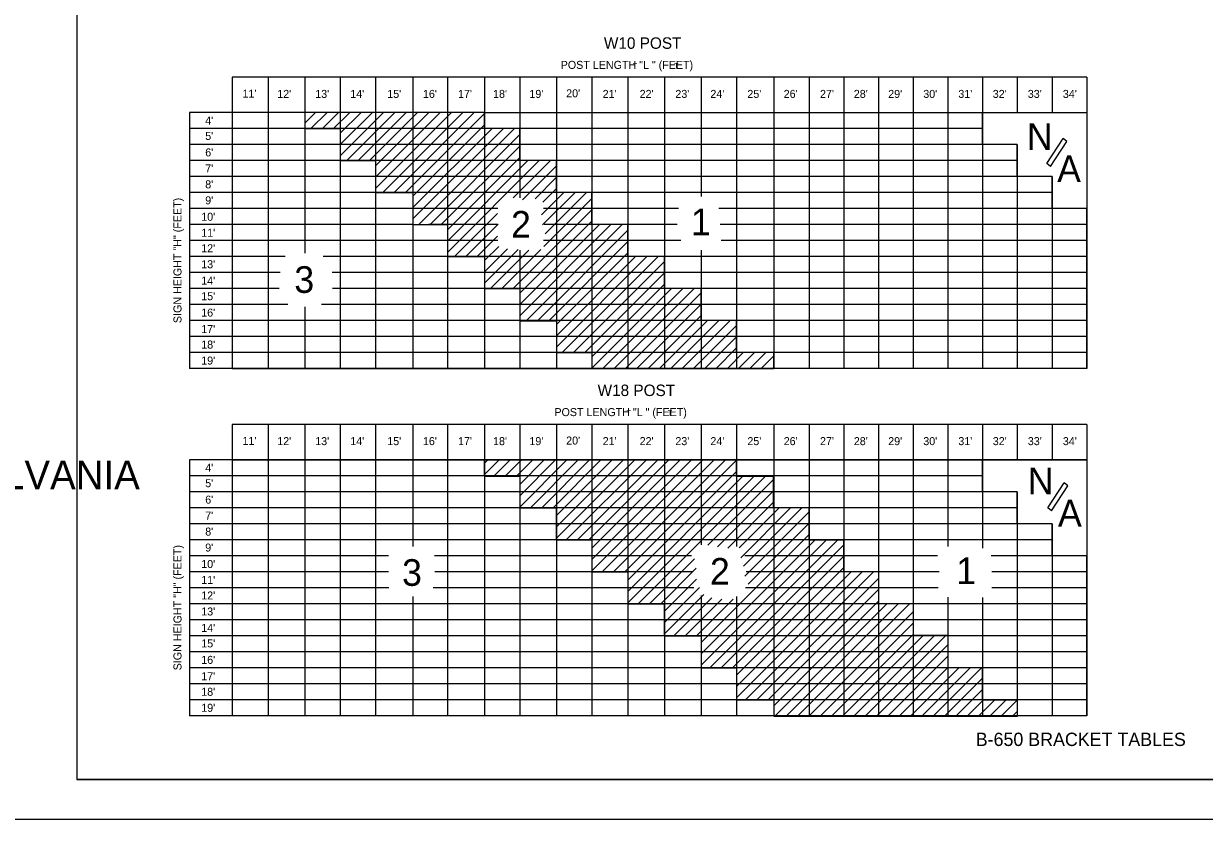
# Model space of a CAD drawing. Extents: x 637580 to 641008, y 294594 to 295782.
# Drawn here: x 639282.3 to 639725, y 294593.6 to 294891.9 of the extents above; entities that cross this region are included whole.
import ezdxf

# ---------------------------------------------------------------- set-up
doc = ezdxf.new("R2010")
doc.units = 0
for name, color, linetype in [('1', 7, 'Continuous'), ('2', 7, 'Continuous'), ('PLT-BNDY', 7, 'Continuous')]:
    doc.layers.add(name, color=color, linetype=linetype)

msp = doc.modelspace()

# ---------------------------------------------------------------- linework, layer by layer
at = {"layer": '1'}
for p, q in [((639302.31, 295172.63), (639302.31, 294608.63)), ((640088.31, 294608.63), (639302.31, 294608.63)), ((639302.31, 294608.63), (639888.31, 294608.63))]:
    msp.add_line(p, q, dxfattribs=at)
at = {"layer": '2'}
for p, q in [((639680.91, 294871.85), (639360.51, 294871.85)), ((639360.51, 294871.85), (639360.51, 294762.59)), ((639374.02, 294871.85), (639374.02, 294762.59)), ((639387.78, 294871.85), (639387.78, 294805.85)), ((639401.03, 294871.85), (639401.03, 294762.59)), ((639414.29, 294871.85), (639414.29, 294762.59)), ((639428.3, 294871.85), (639428.3, 294810.59)), ((639441.3, 294871.85), (639441.3, 294762.59)), ((639455.06, 294871.85), (639455.06, 294762.59)), ((639468.32, 294871.85), (639468.32, 294826.64)), ((639482.07, 294871.85), (639482.07, 294762.59)), ((639495.33, 294871.85), (639495.33, 294762.59)), ((639508.84, 294871.85), (639508.84, 294762.59)), ((639522.6, 294871.85), (639522.6, 294762.59)), ((639536.35, 294871.85), (639536.35, 294827.06)), ((639549.61, 294871.85), (639549.61, 294762.59)), ((639563.62, 294871.85), (639563.62, 294762.59)), ((639576.87, 294871.85), (639576.87, 294762.59)), ((639589.88, 294871.85), (639589.88, 294762.59)), ((639602.88, 294871.85), (639602.88, 294762.59)), ((639615.89, 294871.85), (639615.89, 294762.59)), ((639628.89, 294871.85), (639628.89, 294762.59)), ((639641.9, 294871.85), (639641.9, 294762.59)), ((639654.9, 294871.85), (639654.9, 294858.59)), ((639667.91, 294871.85), (639667.91, 294858.59)), ((639680.91, 294871.85), (639680.91, 294762.59)), ((639344.47, 294858.59), (639344.47, 294762.59)), ((639360.51, 294858.59), (639344.47, 294858.59)), ((639387.78, 294858.59), (639360.51, 294858.59)), ((639393.34, 294858.64), (639387.78, 294858.59)), ((639387.78, 294858.59), (639387.78, 294852.59)), ((639387.78, 294854.56), (639391.81, 294858.59)), ((639390.05, 294852.59), (639396.1, 294858.64)), ((639455.06, 294858.59), (639393.34, 294858.64)), ((639394.34, 294852.64), (639400.34, 294858.64)), ((639398.54, 294852.59), (639404.58, 294858.64)), ((639401.03, 294850.85), (639408.82, 294858.64)), ((639401.03, 294846.61), (639413.07, 294858.64)), ((639401.03, 294842.36), (639417.31, 294858.64)), ((639403.51, 294840.6), (639421.55, 294858.64)), ((639407.76, 294840.6), (639425.79, 294858.64)), ((639412, 294840.6), (639430.04, 294858.64)), ((639414.28, 294838.64), (639434.28, 294858.64)), ((639414.28, 294834.4), (639438.48, 294858.59)), ((639414.28, 294830.15), (639442.72, 294858.59)), ((639416.99, 294828.62), (639446.96, 294858.59)), ((639421.23, 294828.62), (639451.2, 294858.59)), ((639425.48, 294828.62), (639455.06, 294858.21)), ((639455.06, 294852.59), (639455.06, 294858.59)), ((639455.06, 294858.59), (639641.9, 294858.59)), ((639641.9, 294858.59), (639680.91, 294858.59)), ((639641.9, 294846.59), (639641.9, 294858.59)), ((639680.91, 294858.59), (639680.91, 294822.59)), ((639428.28, 294827.19), (639455.1, 294854)), ((639641.9, 294852.59), (639344.47, 294852.59)), ((639387.78, 294852.59), (639401.03, 294852.59)), ((639401.03, 294852.59), (639401.03, 294840.6)), ((639428.28, 294822.95), (639457.94, 294852.6)), ((639428.28, 294818.7), (639462.18, 294852.6)), ((639430.45, 294816.63), (639466.42, 294852.6)), ((639434.69, 294816.63), (639468.25, 294850.18)), ((639468.32, 294852.59), (639455.06, 294852.59)), ((639468.32, 294840.59), (639468.32, 294852.59)), ((639654.9, 294846.59), (639344.47, 294846.59)), ((639438.93, 294816.63), (639468.32, 294846.01)), ((639654.9, 294846.59), (639641.9, 294846.59)), ((639654.9, 294834.59), (639654.9, 294846.59)), ((639654.9, 294846.59), (639654.9, 294762.59)), ((639654.9, 294840.59), (639344.47, 294840.59)), ((639401.03, 294840.6), (639414.29, 294840.6)), ((639414.29, 294840.6), (639414.29, 294828.59)), ((639441.31, 294814.76), (639468.32, 294841.77)), ((639441.31, 294810.52), (639471.39, 294840.59)), ((639441.31, 294806.28), (639475.63, 294840.59)), ((639465.85, 294826.57), (639479.87, 294840.59)), ((639482.08, 294840.59), (639468.32, 294840.59)), ((639482.08, 294828.59), (639482.08, 294840.59)), ((639469.38, 294825.86), (639482.05, 294838.53)), ((639667.91, 294834.59), (639344.47, 294834.59)), ((639474.06, 294826.29), (639482.05, 294834.29)), ((639667.91, 294834.59), (639654.9, 294834.59)), ((639667.91, 294822.59), (639667.91, 294834.59)), ((639667.91, 294834.59), (639667.91, 294762.59)), ((639667.91, 294828.59), (639344.47, 294828.59)), ((639414.29, 294828.59), (639428.3, 294828.59)), ((639428.3, 294828.59), (639428.3, 294816.59)), ((639476.55, 294820.3), (639484.83, 294828.59)), ((639476.92, 294816.43), (639489.08, 294828.59)), ((639477.05, 294825.04), (639482.05, 294830.04)), ((639477.9, 294813.16), (639493.32, 294828.59)), ((639495.31, 294828.59), (639482.08, 294828.59)), ((639495.31, 294816.58), (639495.31, 294828.59)), ((639477.4, 294808.42), (639495.31, 294826.33)), ((639428.3, 294822.59), (639344.47, 294822.59)), ((639460.15, 294822.59), (639428.3, 294822.59)), ((639443.9, 294804.62), (639460, 294820.72)), ((639465.84, 294792.62), (639495.31, 294822.09)), ((639527.82, 294822.59), (639477.23, 294822.59)), ((639680.91, 294822.59), (639543.01, 294822.59)), ((639680.91, 294822.59), (639667.91, 294822.59)), ((639680.91, 294762.59), (639680.91, 294822.59)), ((639428.3, 294816.59), (639344.47, 294816.59)), ((639428.3, 294816.59), (639441.3, 294816.59)), ((639460.15, 294816.59), (639434.07, 294816.59)), ((639441.3, 294816.59), (639441.3, 294804.59)), ((639448.14, 294804.62), (639460.23, 294816.71)), ((639468.33, 294790.87), (639495.31, 294817.85)), ((639468.33, 294786.63), (639498.29, 294816.58)), ((639468.33, 294782.38), (639502.53, 294816.58)), ((639470.74, 294780.55), (639506.78, 294816.58)), ((639474.98, 294780.55), (639508.89, 294814.46)), ((639527.39, 294816.59), (639477.44, 294816.59)), ((639508.84, 294816.58), (639495.31, 294816.58)), ((639508.84, 294804.59), (639508.84, 294816.58)), ((639680.91, 294816.59), (639543.53, 294816.59)), ((639428.3, 294810.59), (639344.47, 294810.59)), ((639428.3, 294810.59), (639428.3, 294762.59)), ((639460.15, 294810.59), (639428.3, 294810.59)), ((639452.39, 294804.62), (639460, 294812.24)), ((639528.67, 294810.59), (639477.23, 294810.59)), ((639479.22, 294780.55), (639508.89, 294810.22)), ((639680.91, 294810.59), (639543.83, 294810.59)), ((639455.08, 294803.07), (639460.44, 294808.43)), ((639455.08, 294798.83), (639463.77, 294807.52)), ((639455.08, 294794.59), (639467.71, 294807.21)), ((639457.35, 294792.62), (639471.78, 294807.05)), ((639461.6, 294792.62), (639476.19, 294807.21)), ((639468.32, 294806.99), (639468.32, 294762.59)), ((639482.07, 294779.15), (639508.89, 294805.97)), ((639536.35, 294806.99), (639536.35, 294762.59)), ((639380.32, 294804.59), (639344.47, 294804.59)), ((639680.91, 294804.59), (639394.62, 294804.59)), ((639441.3, 294804.59), (639455.06, 294804.59)), ((639455.06, 294804.59), (639455.06, 294792.62)), ((639482.07, 294774.91), (639511.79, 294804.63)), ((639482.07, 294770.66), (639516.03, 294804.63)), ((639484.24, 294768.59), (639520.28, 294804.63)), ((639488.48, 294768.59), (639522.64, 294802.75)), ((639522.6, 294804.59), (639508.84, 294804.59)), ((639522.6, 294792.59), (639522.6, 294804.59)), ((639378.48, 294798.59), (639344.47, 294798.59)), ((639680.91, 294798.59), (639397.99, 294798.59)), ((639492.72, 294768.59), (639522.64, 294798.51)), ((639378.07, 294792.59), (639344.47, 294792.59)), ((639680.91, 294792.59), (639398.13, 294792.59)), ((639455.06, 294792.62), (639468.33, 294792.62)), ((639468.33, 294792.62), (639468.33, 294780.55)), ((639495.33, 294766.95), (639522.64, 294794.26)), ((639495.33, 294762.71), (639525.2, 294792.58)), ((639499.45, 294762.59), (639529.44, 294792.58)), ((639503.74, 294762.64), (639533.69, 294792.58)), ((639536.35, 294792.59), (639522.6, 294792.59)), ((639536.35, 294780.59), (639536.35, 294792.59)), ((639507.98, 294762.64), (639536.37, 294791.03)), ((639381.39, 294786.59), (639344.47, 294786.59)), ((639387.78, 294785.78), (639387.78, 294762.59)), ((639680.91, 294786.59), (639393.98, 294786.59)), ((639512.23, 294762.64), (639536.37, 294786.79)), ((639680.91, 294780.59), (639344.47, 294780.59)), ((639468.33, 294780.55), (639482.07, 294780.55)), ((639482.07, 294780.55), (639482.07, 294768.59)), ((639516.47, 294762.64), (639536.37, 294782.54)), ((639520.71, 294762.64), (639538.71, 294780.63)), ((639524.96, 294762.64), (639542.95, 294780.63)), ((639529.2, 294762.64), (639547.19, 294780.63)), ((639533.44, 294762.64), (639549.61, 294778.81)), ((639549.61, 294780.59), (639536.35, 294780.59)), ((639549.61, 294768.59), (639549.61, 294780.59)), ((639680.91, 294774.59), (639344.47, 294774.59)), ((639537.68, 294762.64), (639549.61, 294774.57)), ((639541.93, 294762.64), (639549.61, 294770.33)), ((639680.91, 294768.59), (639344.47, 294768.59)), ((639482.07, 294768.59), (639495.33, 294768.59)), ((639495.33, 294768.59), (639495.33, 294762.59)), ((639546.17, 294762.64), (639552.12, 294768.59)), ((639563.62, 294768.59), (639549.61, 294768.59)), ((639550.41, 294762.64), (639556.36, 294768.59)), ((639554.65, 294762.64), (639560.61, 294768.59)), ((639558.9, 294762.64), (639563.63, 294767.37)), ((639563.62, 294762.59), (639563.62, 294768.59)), ((639680.91, 294762.59), (639344.47, 294762.59)), ((639360.51, 294762.59), (639495.33, 294762.59)), ((639495.33, 294762.59), (639563.62, 294762.59)), ((639563.14, 294762.64), (639563.63, 294763.13)), ((639680.91, 294762.59), (639563.62, 294762.59)), ((639680.91, 294741.69), (639360.51, 294741.69)), ((639360.51, 294741.69), (639360.51, 294632.43)), ((639374.02, 294741.69), (639374.02, 294632.43)), ((639387.78, 294741.69), (639387.78, 294632.43)), ((639401.03, 294741.69), (639401.03, 294632.43)), ((639414.29, 294741.69), (639414.29, 294632.43)), ((639428.3, 294741.69), (639428.3, 294695.92)), ((639441.3, 294741.69), (639441.3, 294632.43)), ((639455.06, 294741.69), (639455.06, 294632.43)), ((639468.32, 294741.69), (639468.32, 294632.43)), ((639482.07, 294741.69), (639482.07, 294632.43)), ((639495.33, 294741.69), (639495.33, 294632.43)), ((639508.84, 294741.69), (639508.84, 294632.43)), ((639522.6, 294741.69), (639522.6, 294632.43)), ((639536.35, 294741.69), (639536.35, 294696.6)), ((639549.61, 294741.69), (639549.61, 294695.97)), ((639563.62, 294741.69), (639563.62, 294632.43)), ((639576.87, 294741.69), (639576.87, 294632.43)), ((639589.88, 294741.69), (639589.88, 294632.43)), ((639602.88, 294741.69), (639602.88, 294632.43)), ((639615.89, 294741.69), (639615.89, 294632.43)), ((639628.89, 294741.69), (639628.89, 294695.97)), ((639641.9, 294741.69), (639641.9, 294695.34)), ((639654.9, 294741.69), (639654.9, 294728.43)), ((639667.91, 294741.69), (639667.91, 294728.43)), ((639680.91, 294741.69), (639680.91, 294632.43)), ((639344.47, 294728.43), (639344.47, 294632.43)), ((639680.91, 294728.43), (639344.47, 294728.43)), ((639360.51, 294728.43), (639455.01, 294728.25)), ((639455.01, 294728.25), (639455.01, 294722.25)), ((639460.51, 294728.25), (639455.01, 294728.25)), ((639455.01, 294727.07), (639456.19, 294728.25)), ((639455.01, 294722.83), (639460.43, 294728.25)), ((639458.68, 294722.25), (639464.67, 294728.24)), ((639549.56, 294728.19), (639460.51, 294728.25)), ((639462.92, 294722.25), (639468.91, 294728.24)), ((639467.16, 294722.25), (639473.15, 294728.24)), ((639468.32, 294719.16), (639477.39, 294728.24)), ((639468.32, 294714.92), (639481.63, 294728.23)), ((639468.32, 294710.68), (639485.87, 294728.23)), ((639472.32, 294710.44), (639490.12, 294728.23)), ((639476.57, 294710.44), (639494.36, 294728.23)), ((639480.81, 294710.44), (639498.6, 294728.22)), ((639482.03, 294707.41), (639502.84, 294728.22)), ((639482.03, 294703.17), (639507.08, 294728.22)), ((639482.03, 294698.93), (639511.32, 294728.22)), ((639485.78, 294698.44), (639515.56, 294728.21)), ((639490.02, 294698.44), (639519.8, 294728.21)), ((639494.26, 294698.44), (639524.04, 294728.21)), ((639495.31, 294695.24), (639528.28, 294728.21)), ((639495.31, 294691), (639532.52, 294728.2)), ((639495.31, 294686.75), (639536.76, 294728.2)), ((639499.21, 294686.41), (639541, 294728.2)), ((639503.45, 294686.41), (639545.24, 294728.2)), ((639507.7, 294686.41), (639549.48, 294728.19)), ((639549.56, 294722.13), (639549.56, 294728.19)), ((639549.61, 294728.43), (639641.9, 294728.43)), ((639641.9, 294728.43), (639680.91, 294728.43)), ((639641.9, 294716.43), (639641.9, 294728.43)), ((639680.91, 294728.43), (639680.91, 294692.43)), ((639641.9, 294722.43), (639344.47, 294722.43)), ((639455.01, 294722.25), (639468.32, 294722.25)), ((639468.32, 294722.25), (639468.32, 294710.44)), ((639508.81, 294683.29), (639549.56, 294724.03)), ((639508.81, 294679.04), (639551.9, 294722.13)), ((639508.81, 294674.8), (639556.14, 294722.13)), ((639512.71, 294674.45), (639560.38, 294722.13)), ((639538.91, 294696.41), (639563.49, 294720.99)), ((639563.49, 294722.13), (639549.56, 294722.13)), ((639563.49, 294710.39), (639563.49, 294722.13)), ((639542.52, 294695.79), (639563.49, 294716.75)), ((639654.9, 294716.43), (639344.47, 294716.43)), ((639546.33, 294695.35), (639563.49, 294712.5)), ((639654.9, 294716.43), (639641.9, 294716.43)), ((639654.9, 294704.43), (639654.9, 294716.43)), ((639654.9, 294716.43), (639654.9, 294632.43)), ((639654.9, 294710.43), (639344.47, 294710.43)), ((639468.32, 294710.44), (639482.03, 294710.44)), ((639482.03, 294710.44), (639482.03, 294698.44)), ((639550.61, 294695.39), (639565.62, 294710.39)), ((639551.18, 294691.72), (639569.86, 294710.39)), ((639552.21, 294688.5), (639574.1, 294710.39)), ((639552.73, 294684.78), (639576.9, 294708.94)), ((639576.9, 294710.39), (639563.49, 294710.39)), ((639576.9, 294698.33), (639576.9, 294710.39)), ((639667.91, 294704.43), (639344.47, 294704.43)), ((639553.97, 294681.78), (639576.9, 294704.7)), ((639667.91, 294704.43), (639654.9, 294704.43)), ((639667.91, 294692.43), (639667.91, 294704.43)), ((639667.91, 294704.43), (639667.91, 294632.43)), ((639536.32, 294659.88), (639576.9, 294700.46)), ((639667.91, 294698.43), (639344.47, 294698.43)), ((639482.03, 294698.44), (639495.31, 294698.44)), ((639495.31, 294698.44), (639495.31, 294686.41)), ((639536.32, 294655.64), (639579.01, 294698.33)), ((639536.32, 294651.4), (639583.25, 294698.33)), ((639539.64, 294650.48), (639587.49, 294698.33)), ((639543.88, 294650.48), (639589.9, 294696.49)), ((639589.9, 294698.33), (639576.9, 294698.33)), ((639589.9, 294686.4), (639589.9, 294698.33)), ((639419.17, 294692.43), (639344.47, 294692.43)), ((639532.71, 294692.43), (639436.35, 294692.43)), ((639516.95, 294674.45), (639533.83, 294691.34)), ((639548.13, 294650.48), (639589.9, 294692.25)), ((639625.02, 294692.43), (639552.77, 294692.43)), ((639680.91, 294692.43), (639645.09, 294692.43)), ((639680.91, 294692.43), (639667.91, 294692.43)), ((639680.91, 294632.43), (639680.91, 294692.43)), ((639419.11, 294686.43), (639344.47, 294686.43)), ((639533.13, 294686.43), (639436.54, 294686.43)), ((639495.31, 294686.41), (639508.81, 294686.41)), ((639508.81, 294686.41), (639508.81, 294674.45)), ((639521.19, 294674.45), (639534.51, 294687.77)), ((639549.6, 294647.7), (639589.9, 294688)), ((639549.6, 294643.46), (639592.54, 294686.4)), ((639549.6, 294639.22), (639596.78, 294686.4)), ((639553.02, 294638.4), (639601.02, 294686.4)), ((639625.65, 294686.43), (639553.2, 294686.43)), ((639602.96, 294686.4), (639589.9, 294686.4)), ((639602.96, 294674.38), (639602.96, 294686.4)), ((639680.91, 294686.43), (639645.3, 294686.43)), ((639522.53, 294671.54), (639534.66, 294683.68)), ((639557.26, 294638.4), (639602.96, 294684.1)), ((639419.3, 294680.43), (639344.47, 294680.43)), ((639428.3, 294677.11), (639428.3, 294632.43)), ((639533.55, 294680.43), (639435.89, 294680.43)), ((639522.53, 294667.3), (639535.71, 294680.49)), ((639522.53, 294663.06), (639537.32, 294677.86)), ((639526.15, 294662.44), (639540.33, 294676.62)), ((639536.35, 294677.58), (639536.35, 294632.43)), ((639549.61, 294677.16), (639549.61, 294632.43)), ((639625.23, 294680.43), (639552.99, 294680.43)), ((639561.51, 294638.4), (639602.96, 294679.86)), ((639628.89, 294676.95), (639628.89, 294632.43)), ((639641.9, 294676.74), (639641.9, 294632.43)), ((639680.91, 294680.43), (639645.3, 294680.43)), ((639387.78, 294674.43), (639344.47, 294674.43)), ((639680.91, 294674.43), (639387.78, 294674.43)), ((639508.81, 294674.45), (639522.53, 294674.45)), ((639522.53, 294674.45), (639522.53, 294662.44)), ((639530.4, 294662.44), (639544.13, 294676.18)), ((639534.64, 294662.44), (639548.41, 294676.22)), ((639563.6, 294636.25), (639602.96, 294675.61)), ((639563.96, 294632.37), (639605.98, 294674.38)), ((639568.2, 294632.37), (639610.22, 294674.38)), ((639572.44, 294632.37), (639614.46, 294674.38)), ((639615.91, 294674.38), (639602.96, 294674.38)), ((639615.91, 294662.51), (639615.91, 294674.38)), ((639387.78, 294668.43), (639344.47, 294668.43)), ((639680.91, 294668.43), (639387.78, 294668.43)), ((639576.69, 294632.37), (639615.91, 294671.59)), ((639580.93, 294632.37), (639615.91, 294667.35)), ((639387.78, 294662.43), (639344.47, 294662.43)), ((639680.91, 294662.43), (639387.78, 294662.43)), ((639522.53, 294662.44), (639536.32, 294662.44)), ((639536.32, 294662.44), (639536.32, 294650.48)), ((639585.17, 294632.37), (639615.91, 294663.1)), ((639589.41, 294632.37), (639619.56, 294662.51)), ((639593.66, 294632.37), (639623.8, 294662.51)), ((639597.9, 294632.37), (639628.04, 294662.51)), ((639602.14, 294632.37), (639628.93, 294659.15)), ((639628.93, 294662.51), (639615.91, 294662.51)), ((639628.93, 294650.49), (639628.93, 294662.51)), ((639387.78, 294656.43), (639344.47, 294656.43)), ((639680.91, 294656.43), (639387.78, 294656.43)), ((639606.39, 294632.37), (639628.93, 294654.91)), ((639680.91, 294650.43), (639344.47, 294650.43)), ((639536.32, 294650.48), (639549.6, 294650.48)), ((639549.6, 294650.48), (639549.6, 294638.4)), ((639610.63, 294632.37), (639628.93, 294650.67)), ((639614.87, 294632.37), (639633, 294650.49)), ((639619.11, 294632.37), (639637.24, 294650.49)), ((639623.36, 294632.37), (639641.48, 294650.49)), ((639641.78, 294650.49), (639628.93, 294650.49)), ((639641.78, 294638.33), (639641.78, 294650.49)), ((639627.6, 294632.37), (639641.78, 294646.54)), ((639680.91, 294644.43), (639344.47, 294644.43)), ((639631.84, 294632.37), (639641.78, 294642.3)), ((639680.91, 294638.43), (639344.47, 294638.43)), ((639549.6, 294638.4), (639563.6, 294638.4)), ((639563.6, 294638.4), (639563.6, 294632.37)), ((639636.08, 294632.37), (639642.05, 294638.33)), ((639640.33, 294632.37), (639646.29, 294638.33)), ((639654.94, 294638.33), (639641.78, 294638.33)), ((639644.57, 294632.37), (639650.54, 294638.33)), ((639648.81, 294632.37), (639654.78, 294638.33)), ((639654.94, 294632.37), (639654.94, 294638.33)), ((639680.91, 294632.43), (639344.47, 294632.43)), ((639563.62, 294632.43), (639360.51, 294632.43)), ((639563.6, 294632.37), (639654.94, 294632.37)), ((639653.05, 294632.37), (639654.94, 294634.25)), ((639680.91, 294632.43), (639654.9, 294632.43))]:
    msp.add_line(p, q, dxfattribs=at)
for points in [[(639665.96, 294839.44), (639672.1, 294848.89)], [(639667.38, 294838.33), (639673.52, 294847.78)], [(639673.52, 294847.78), (639672.1, 294848.89)], [(639667.38, 294838.33), (639665.96, 294839.44)], [(639666.28, 294710.36), (639672.42, 294719.8)], [(639667.7, 294709.25), (639673.84, 294718.7)], [(639673.84, 294718.7), (639672.42, 294719.8)], [(639667.7, 294709.25), (639666.28, 294710.36)]]:
    msp.add_lwpolyline(points, dxfattribs=at)
at = {"layer": 'PLT-BNDY'}
msp.add_lwpolyline([(639262.31, 295187.63), (640103.31, 295187.63), (640103.31, 294593.63), (639262.31, 294593.63)], close=True, dxfattribs=at)

# ---------------------------------------------------------------- texts
at = {"layer": '1'}
msp.add_text('COMMONWEALTH OF PENNSYLVANIA', height=10.7828, dxfattribs=at).set_placement((639059.9, 294717.36))
at = {"layer": '2'}
for s, height, p in [('W10 POST', 4.3, (639499.89, 294882.47)), ('POST LENGTH "L " (FEET)', 3, (639483.69, 294874.95)), ('T', 2, (639510.72, 294875.12)), ('T', 2, (639526.21, 294875.12)), ("11'", 3, (639364.38, 294864.18)), ("12'", 3, (639377.42, 294864.07)), ("13'", 3, (639391.66, 294864.07)), ("14'", 3, (639404.8, 294864.07)), ("15'", 3, (639418.66, 294864.07)), ("16'", 3, (639432.04, 294864.07)), ("17'", 3, (639445.19, 294864.07)), ("18'", 3, (639458.33, 294864.07)), ("19'", 3, (639471.95, 294864.07)), ("20'", 3, (639485.74, 294864.29)), ("21'", 3, (639499.43, 294864.07)), ("22'", 3, (639513.29, 294864.07)), ("23'", 3, (639526.68, 294864.07)), ("24'", 3, (639539.82, 294864.07)), ("25'", 3, (639553.68, 294864.07)), ("26'", 3, (639567.3, 294864.07)), ("27'", 3, (639580.92, 294864.07)), ("28'", 3, (639593.59, 294864.07)), ("29'", 3, (639606.49, 294864.07)), ("30'", 3, (639619.64, 294864.07)), ("31'", 3, (639632.78, 294864.07)), ("32'", 3, (639645.69, 294864.07)), ("33'", 3, (639658.83, 294864.07)), ("34'", 3, (639671.97, 294864.07)), ('N', 10, (639658.46, 294844.6)), ('A', 10, (639669.83, 294832.49)), ("10'", 3, (639348.91, 294818.01)), ('2', 10, (639465.07, 294811.68)), ('1', 10, (639532.52, 294812.6)), ("11'", 3, (639348.91, 294812.03)), ("12'", 3, (639348.91, 294806.21)), ("13'", 3, (639348.91, 294800.22)), ('3', 10, (639383.81, 294790.98)), ("14'", 3, (639348.91, 294794.06)), ("15'", 3, (639348.91, 294788.25)), ("16'", 3, (639348.91, 294782.08)), ("17'", 3, (639348.91, 294775.92)), ("18'", 3, (639348.91, 294770.11)), ("19'", 3, (639348.91, 294764.12)), ('W18 POST', 4.3, (639497.53, 294752.31)), ('POST LENGTH "L " (FEET)', 3, (639481.33, 294744.79)), ('T', 2, (639508.35, 294744.96)), ('T', 2, (639523.85, 294744.96)), ("11'", 3, (639364.38, 294734.02)), ("12'", 3, (639377.42, 294733.91)), ("13'", 3, (639391.66, 294733.91)), ("14'", 3, (639404.8, 294733.91)), ("15'", 3, (639418.66, 294733.91)), ("16'", 3, (639432.04, 294733.91)), ("17'", 3, (639445.19, 294733.91)), ("18'", 3, (639458.33, 294733.91)), ("19'", 3, (639471.95, 294733.91)), ("20'", 3, (639485.74, 294734.13)), ("21'", 3, (639499.43, 294733.91)), ("22'", 3, (639513.29, 294733.91)), ("23'", 3, (639526.68, 294733.91)), ("24'", 3, (639539.82, 294733.91)), ("25'", 3, (639553.68, 294733.91)), ("26'", 3, (639567.3, 294733.91)), ("27'", 3, (639580.92, 294733.91)), ("28'", 3, (639593.59, 294733.91)), ("29'", 3, (639606.49, 294733.91)), ("30'", 3, (639619.64, 294733.91)), ("31'", 3, (639632.78, 294733.91)), ("32'", 3, (639645.69, 294733.91)), ("33'", 3, (639658.83, 294733.91)), ("34'", 3, (639671.97, 294733.91)), ('N', 10, (639658.78, 294715.52)), ('A', 10, (639670.15, 294703.41)), ("10'", 3, (639348.91, 294687.85)), ('3', 10, (639424.21, 294681.16)), ('2', 10, (639539.65, 294681.59)), ('1', 10, (639631.97, 294681.82)), ("11'", 3, (639348.91, 294681.86)), ("12'", 3, (639348.91, 294676.05)), ("13'", 3, (639348.91, 294670.06)), ("14'", 3, (639348.91, 294663.9)), ("15'", 3, (639348.91, 294658.09)), ("16'", 3, (639348.91, 294651.92)), ("17'", 3, (639348.91, 294645.76)), ("18'", 3, (639348.91, 294639.95)), ("19'", 3, (639348.91, 294633.96)), ('B-650 BRACKET TABLES', 5, (639639.3, 294621.13))]:
    msp.add_text(s, height=height, dxfattribs=at).set_placement(p)
for s, rotation, p in [("4'", 360, (639350.41, 294854.07)), ("5'", 360, (639350.41, 294848.31)), ("6'", 360, (639350.41, 294842.14)), ("7'", 360, (639350.41, 294836.16)), ("8'", 360, (639350.41, 294830.17)), ("9'", 360, (639350.41, 294824.18)), ('SIGN HEIGHT "H" (FEET)', 90, (639341.5, 294779.65)), ("4'", 360, (639350.41, 294723.91)), ("5'", 360, (639350.41, 294718.15)), ("6'", 360, (639350.41, 294711.98)), ("7'", 360, (639350.41, 294705.99)), ("8'", 360, (639350.41, 294700.01)), ('SIGN HEIGHT "H" (FEET)', 90, (639341.5, 294649.49)), ("9'", 360, (639350.41, 294694.02))]:
    msp.add_text(s, height=3, rotation=rotation, dxfattribs=at).set_placement(p)

doc.saveas('drawing.dxf')
